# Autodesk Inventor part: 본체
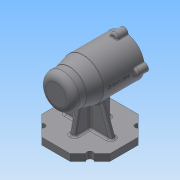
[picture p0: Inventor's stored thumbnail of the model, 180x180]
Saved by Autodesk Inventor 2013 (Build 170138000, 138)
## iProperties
Created: 2021-01
Part Number: 본체
Material: 일반
Document SubType Name: Modeling
Designer: Administrator
Density: 1 g/cm^3
Author: Administrator
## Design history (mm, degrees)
sketch "스케치1" dims "d0" = 100
  geometry: L1 (20.711, 50)-(50, 20.711); L2 (50, 20.711)-(50, -20.711); L3 (50, -20.711)-(20.711, -50); L4 (20.711, -50)-(-20.711, -50); L5 (-20.711, -50)-(-50, -20.711); L6 (-50, -20.711)-(-50, 20.711); L7 (-50, 20.711)-(-20.711, 50); L8 (-20.711, 50)-(20.711, 50); 4 further points
  constraints: 16 end point, 2 coincident, 2 vertical alignment, 1 midpoint, 19 other
extrude "돌출1" new body sketch "스케치1" distance "d2" = 10; taper "d3" = 0 deg
sketch "스케치2"
  geometry: L1 (50, 75)-(-50, 75); L2 (-20.711, 0)-(20.711, 0) reference; L3 (-10, 105)-(-30, 100); L4 (-30, 100)-(-40, 100); L5 (-50, 90)-(-50, 75); L6 (-10, 105)-(50, 105); L7 (50, 105)-(50, 75); A1 r 10 centre (-40, 90) between (-40, 100) and (-50, 90); 2 further points
  constraints: 12 end point, 2 point on circle, 2 tangent, 2 vertical, 1 centre point, 1 horizontal, 1 perpendicular, 1 vertical alignment
  dimensions: "d4" = 75 distance between parallel lines of L2 L1; "d5" = 100 distance of L1.start L1.end; "d7" = 20 distance from line of L3.end L5; "d8" = 40 distance from line of L3.start L5; "d9" = 50 diameter of L4 L1; "d10" = 60 diameter of L6 L1; "d11" = 10 radius of A1
revolve "회전1" sketch "스케치2" stored, may be unused: angle "d12" = 90 deg
sketch "스케치3"
  geometry: L1 (50, 45)-(50, 105) reference; L2 (-20.711, 0)-(20.711, 0) reference; L3 (-0.939, 98.948)-(-0.939, 98.601); L4 (-50, 60)-(-50, 90) reference; L5 (50, 75)-(-50, 75); L6 (50, 96)-(35, 96); L7 (35, 96)-(35, 99); L8 (35, 99)-(-7, 99); L9 (-7, 99)-(-7, 96); L10 (-7, 96)-(-19, 96); L11 (-19, 96)-(-19, 92.5); L12 (-19, 92.5)-(-37, 92.5); L13 (-37, 92.5)-(-37, 91); L14 (-37, 91)-(-41, 91); L15 (-41, 91)-(-41, 85.5); L16 (-41, 85.5)-(-41, 85.5); L17 (-44, 82.5)-(-44, 75); A1 r 3 centre (-41, 82.5) between (-41, 85.5) and (-44, 82.5); 2 further points
  constraints: 28 end point, 7 perpendicular, 5 parallel, 4 point on line, 2 midpoint, 2 point on circle, 2 tangent, 1 centre point
  dimensions: "d15" = 15 distance of L6.start L6.end; "d17" = 42 distance of L7.end L8.end; "d18" = 12 distance of L9.end L10.end; "d19" = 18 distance of L11.end L12.end; "d20" = 4 distance of L13.end L14.end; "d21" = 3 distance of L15.end point (-44, 85.5); "d22" = 42 diameter of L6 L5; "d23" = 48 diameter of L8 L5; "d24" = 42 diameter of L10 L5; "d25" = 35 diameter of L12 L5; "d26" = 32 diameter of L14 L5; "d27" = 21 diameter of L16 L5; "d28" = 3 radius of A1
revolve "회전2" sketch "스케치3" stored, may be unused: angle "d29" = 90 deg
sketch "스케치4"
  geometry: L1 (-30, 50)-(-10, 45) reference; L2 (-20.711, 10)-(-50, 10) reference; L3 (20.711, 10)-(-20.711, 10) reference; L4 (50, 10)-(20.711, 10) reference; L5 (-10, 45)-(50, 45) reference; L6 (-19.27, 49.77)-(-27, 10); L7 (-19.27, 49.77)-(27, 49.77); L8 (27, 49.77)-(27, 10); 1 further point
  constraints: 6 end point, 2 point on line, 1 parallel, 1 perpendicular
  dimensions: "d30" = 101 deg angle of L2 L6; "d31" = 23 distance of L2.end L6.end; "d32" = 23 distance of L4.start L8.end; "d99" = 46.2695 distance of L6.start L7.end
extrude "돌출2" join sketch "스케치4" stored distance "d34" = 8; taper "d35" = 0 deg
sketch "스케치5"
  geometry: L1 (20.711, 10)-(-20.711, 10) reference; L2 (-20.711, 10)-(-50, 10) reference; L3 (50, 10)-(20.711, 10) reference; L4 (-19.606, 52.293)-(-35, 10); L5 (19.606, 52.293)-(35, 10); A1 r 30 centre (0, 75) between (4, 45.268) and (-4, 45.268) reference; 1 further point
  constraints: 4 end point, 2 point on circle, 2 point on line
  dimensions: "d37" = 15 distance of L2.end L4.end; "d38" = 110 deg angle of L2 L4; "d45" = 15 distance of L3.start L5.end; "d46" = 110 deg angle of L3 L5
feature "리브1" dims "d39" = 1, "d40" = 8, "d41" = 0, "d42" = 0, "d43" = 1, "d44" = 1
feature "리브2" dims "d47" = 1, "d48" = 8, "d49" = 0, "d50" = 0, "d51" = 1, "d52" = 1
sketch "스케치6"
  geometry: L1 (0, 0)-(0, 50); L2 (0, 0)-(-35.355, 35.355); L3 (0, 0)-(35.355, 35.355); L4 (0, 0)-(-42.323, -42.323); L5 (0, 0)-(46.839, -46.839); L6 (0, 0)-(0, -67.844); L7 (-20.711, -50)-(-50, -20.711) reference; L8 (50, -20.711)-(20.711, -50) reference; C1 r 4.5 at (-35.355, 35.355); C2 r 4.5 at (35.355, 35.355); C3 r 4.5 at (-35.355, -35.355); C4 r 4.5 at (35.355, -35.355); A1 r 50 centre (0, 0) between (0, 50) and (-35.355, 35.355); 1 further point
  constraints: 12 end point, 5 centre point, 3 coincident, 3 point on circle, 2 collinear, 2 midpoint, 1 horizontal alignment, 1 vertical
  dimensions: "d53" = 100 diameter of A1; "d56" = 45 deg angle of L1 L2; "d58" = 45 deg angle of L3 L1; "d60" = 9 diameter of C1; "d61" = 9 diameter of C2; "d62" = 45 deg angle of L6 L5; "d63" = 9 diameter of C3; "d64" = 9 diameter of C4
extrude "돌출3" cut sketch "스케치6" stored distance "d65" = 8; taper "d66" = 0 deg
sketch "스케치8"
  geometry: A1 r 30 centre (0, 0) between (-4, 29.732) and (4, 29.732) reference; A2 r 6 centre (0, -30) between (-5.97, -29.4) and (5.97, -29.4); A3 r 6 centre (-30, 0) between (-29.4, 5.97) and (-29.4, -5.97); A4 r 6 centre (30, 0) between (29.4, -5.97) and (29.4, 5.97); A5 r 6 centre (0, 30) between (5.97, 29.4) and (-5.97, 29.4); 6 further points
  constraints: 12 point on circle, 4 centre point, 4 coincident, 2 horizontal alignment, 2 vertical alignment, 12 other
  dimensions: "d69" = 12 diameter of A2; "d71" = 12 diameter of A4; "d72" = 12 diameter of A3; "d73" = 12 diameter of A5
extrude "돌출4" join sketch "스케치8" distance "d74" = 16; taper "d75" = 0 deg
sketch "스케치9"
  geometry: C1 r 21 at (0, -30) reference; 2 further points
  constraints: 1 vertical alignment
  dimensions: "d78" = 30 distance of C1.centre point (0, -60)
hole "구멍1" sketch "스케치9" at (0, -60) diameter "d79" = 3.242; stored, may be unused: countersink angle "d83" = 90 deg, drill point angle "d85" = 118 deg; dims "d80" = 8, "d81" = 4, "d82" = 2, "d84" = 10
node "작업 평면3"
sketch "스케치12"
  geometry: L1 (30, 29.4)-(30, 36) reference; L2 (30, -6)-(30, 6) reference; 5 further points
  constraints: 1 horizontal alignment, 1 midpoint, 1 other
  dimensions: "d89" = 38 distance from line of L1 point (-8, 0)
feature "엠보싱1" sketch "스케치12" dims "d4" = 75, "d5" = 100, "d7" = 20, "d8" = 40, "d9" = 50, "d10" = 60, "d11" = 10, "d90" = 0.5, "d91" = 0
fillet "모깎기1" dims "d92" = 3
fillet "모깎기2" dims "d93" = 3
fillet "모깎기3" dims "d94" = 3
fillet "모깎기4" dims "d95" = 3, "d96" = 0.3
fillet "모깎기5" dims "d97" = 3
fillet "모깎기6" dims "d98" = 1
node "솔리드1"
pattern_circular "원형 패턴1" dims angle "d87" = 360 deg
